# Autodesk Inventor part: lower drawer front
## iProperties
Created: 2005-05
Part Number: lower drawer front
Material: Default
Document SubType Name: Modeling
Designer: a.campbell
Manufacturer: Standard
Standards Organization: Custom
Author: a.campbell
Comments: machine to detail
length: 1
thickness: 1
width: 1
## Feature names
1. Extrusion1
2. Extrusion2
